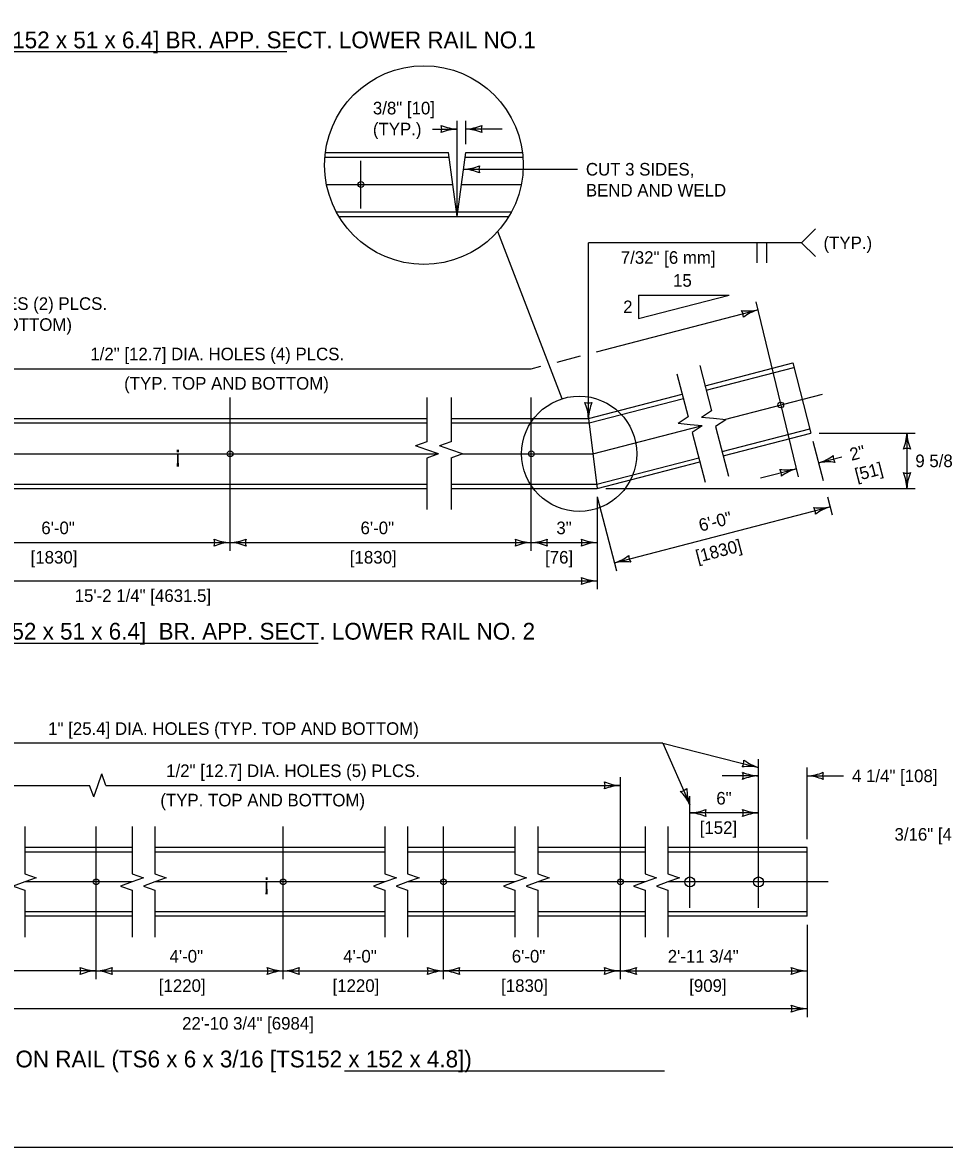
# Model space of a CAD drawing. Extents: x 49991.4 to 50021, y 49987.6 to 50011.4.
# Drawn here: x 50001.47 to 50005.86, y 49987.8 to 49993.16 of the extents above; entities that cross this region are included whole.
import ezdxf

# ---------------------------------------------------------------- set-up
doc = ezdxf.new("R2010")
doc.units = 0
for name, color, linetype in [('Level 1', 7, 'Continuous'), ('Level 2', 7, 'Continuous'), ('Level 3', 7, 'Continuous'), ('Level 4', 7, 'Continuous'), ('Level 5', 7, 'Continuous'), ('Level 6', 7, 'Continuous')]:
    doc.layers.add(name, color=color, linetype=linetype)

msp = doc.modelspace()

# ---------------------------------------------------------------- linework, layer by layer
at = {"layer": 'Level 1'}
for p, q in [((50002.9115, 49992.5433), (50003.499, 49992.5433)), ((50003.5403, 49992.2385), (50003.499, 49992.5433)), ((50003.5403, 49992.2385), (50003.5815, 49992.5433)), ((50003.5815, 49992.5433), (50003.8516, 49992.5433)), ((50002.9761, 49992.2385), (50003.787, 49992.2385)), ((50004.7222, 49991.4315), (50005.14, 49991.5399)), ((50005.14, 49991.5399), (50005.2267, 49991.2054)), ((50004.1662, 49991.2758), (50004.6135, 49991.3919)), ((50001.2445, 49991.2758), (50003.3956, 49991.2758)), ((50003.5108, 49991.2758), (50004.1662, 49991.2758)), ((50004.1662, 49991.2758), (50004.2084, 49990.9411)), ((50004.8089, 49991.0969), (50005.2267, 49991.2054)), ((50004.2084, 49990.9411), (50004.6974, 49991.068)), ((50001.2445, 49990.9411), (50003.3956, 49990.9411)), ((50003.5108, 49990.9411), (50004.2084, 49990.9411)), ((50001.9899, 49989.2289), (50001.4778, 49989.2289)), ((50003.1953, 49989.2289), (50002.0985, 49989.2289)), ((50003.8159, 49989.2289), (50003.3039, 49989.2289)), ((50004.4366, 49989.2289), (50003.9245, 49989.2289)), ((50005.2095, 49989.2289), (50004.5452, 49989.2289)), ((50005.2095, 49988.9014), (50005.2095, 49989.2289)), ((50001.9899, 49988.9014), (50001.4778, 49988.9014)), ((50003.1953, 49988.9014), (50002.0985, 49988.9014)), ((50003.8159, 49988.9014), (50003.3039, 49988.9014)), ((50004.4366, 49988.9014), (50003.9245, 49988.9014)), ((50005.2095, 49988.9014), (50004.5452, 49988.9014))]:
    msp.add_line(p, q, dxfattribs=at)
msp.add_lwpolyline([(49999.3835, 49998.9992), (50016.7501, 49998.9992), (50016.7501, 49987.7988), (49999.3835, 49987.7988)], close=True, dxfattribs=at)
for centre, radius in [((50003.0813, 49992.3909), 0.0137), ((50005.0833, 49991.3395), 0.0137), ((50002.4573, 49991.107), 0.0137), ((50003.8938, 49991.107), 0.0137), ((50001.8186, 49989.0651), 0.0136), ((50002.7107, 49989.0651), 0.0136), ((50003.4751, 49989.0651), 0.0136), ((50004.3186, 49989.0651), 0.0136), ((50004.65, 49989.0651), 0.0239), ((50004.9775, 49989.0651), 0.0239)]:
    msp.add_circle(centre, radius, dxfattribs=at)
at = {"layer": 'Level 2'}
for p, q in [((50001.1941, 49993.0245), (50002.7276, 49993.0245)), ((50001.111, 49990.2046), (50002.8772, 49990.2046)), ((50003.0022, 49988.1651), (50004.5293, 49988.1651))]:
    msp.add_line(p, q, dxfattribs=at)
at = {"layer": 'Level 3'}
for p, q in [((50003.5815, 49992.5833), (50003.5815, 49992.6954)), ((50003.422, 49992.6554), (50003.5403, 49992.6554)), ((50003.7549, 49992.6554), (50003.5815, 49992.6554)), ((50003.5707, 49992.4638), (50004.114, 49992.4638)), ((50004.0412, 49991.3694), (50003.7341, 49992.1672)), ((50005.1824, 49992.113), (50005.2489, 49992.1795)), ((50004.1662, 49991.2758), (50004.1665, 49992.113)), ((50005.1824, 49992.113), (50004.1665, 49992.113)), ((50004.9691, 49992.113), (50004.9691, 49992.0178)), ((50005.0148, 49992.113), (50005.0148, 49992.0178)), ((50005.1824, 49992.113), (50005.2489, 49992.0472)), ((50004.4056, 49991.8636), (50004.8375, 49991.8636)), ((50004.4056, 49991.8636), (50004.4056, 49991.7513)), ((50004.4056, 49991.7513), (50004.8375, 49991.8636)), ((50004.205, 49991.5936), (50004.9743, 49991.7932)), ((50004.0164, 49991.5446), (50004.1276, 49991.5735)), ((50001.034, 49991.5128), (50003.8938, 49991.5128)), ((50003.8938, 49991.5128), (50003.9389, 49991.5245)), ((50005.2667, 49991.2054), (50005.7249, 49991.2054)), ((50005.6849, 49991.2054), (50005.6849, 49990.9411)), ((50005.2368, 49991.1667), (50005.2853, 49990.9798)), ((50005.2637, 49991.0633), (50005.3746, 49991.0921)), ((50004.9871, 49990.9915), (50005.1564, 49991.0355)), ((50004.2084, 49990.9011), (50004.2084, 49990.4606)), ((50004.2084, 49990.9011), (50004.2084, 49990.8999)), ((50004.2084, 49990.9011), (50004.3, 49990.5483)), ((50004.2484, 49990.9411), (50005.7249, 49990.9411)), ((50005.3054, 49990.9024), (50005.3281, 49990.8151)), ((50004.2899, 49990.5871), (50005.318, 49990.8539)), ((50000.8491, 49990.6835), (50002.4573, 49990.6835)), ((50002.4573, 49990.6835), (50003.8938, 49990.6835)), ((50003.8938, 49990.6835), (50004.2084, 49990.6835)), ((50000.0841, 49990.5006), (50004.2084, 49990.5006)), ((50004.5215, 49989.7265), (50000.7474, 49989.7265)), ((50004.5215, 49989.7265), (50004.65, 49989.4343)), ((50004.5215, 49989.7265), (50004.9775, 49989.611)), ((50001.8262, 49989.5254), (50001.8456, 49989.5802)), ((50001.8651, 49989.5254), (50001.8456, 49989.5802)), ((50004.9775, 49989.571), (50004.8041, 49989.571)), ((50005.2095, 49989.2689), (50005.2095, 49989.611)), ((50005.2095, 49989.571), (50005.3829, 49989.571)), ((50000.975, 49989.5254), (50001.7874, 49989.5254)), ((50001.8068, 49989.4706), (50001.7874, 49989.5254)), ((50001.8068, 49989.4706), (50001.8262, 49989.5254)), ((50001.8651, 49989.5254), (50004.3186, 49989.5254)), ((50004.9775, 49989.3943), (50004.65, 49989.3943)), ((50005.2095, 49988.8614), (50005.2094, 49988.4208)), ((50001.8186, 49988.6408), (50000.975, 49988.6408)), ((50001.8186, 49988.6408), (50002.7107, 49988.6408)), ((50002.7107, 49988.6408), (50003.4751, 49988.6408)), ((50004.3186, 49988.6408), (50003.4751, 49988.6408)), ((50004.3186, 49988.6408), (50005.2095, 49988.6408)), ((50005.2094, 49988.4608), (50000.0842, 49988.4608))]:
    msp.add_line(p, q, dxfattribs=at)
for centre, radius in [((50003.3815, 49992.4837), 0.4738), ((50004.1222, 49991.107), 0.2747)]:
    msp.add_circle(centre, radius, dxfattribs=at)
for centre, radius, start, end in [((50003.4121, 49992.6554), 0.0548, 342.1388, 17.8612), ((50003.5518, 49992.8881), 0.233, 247.9228, 267.1727), ((50003.5723, 49992.8776), 0.2223, 272.3605, 292.544), ((50003.7097, 49992.6554), 0.0548, 162.1388, 197.8612), ((50003.5494, 49992.4333), 0.2223, 92.3605, 112.544), ((50003.57, 49992.4227), 0.233, 67.9228, 87.1727), ((50003.5616, 49992.6859), 0.2223, 272.3605, 292.544), ((50003.5592, 49992.231), 0.233, 67.9228, 87.1727), ((50003.6989, 49992.4638), 0.0548, 162.1388, 197.8612), ((50004.9274, 49992.0105), 0.2223, 262.0039, 282.1874), ((50004.8502, 49991.761), 0.0548, 356.6867, 32.4091), ((50005.0439, 49991.5709), 0.233, 107.3752, 126.6251), ((50003.944, 49991.2667), 0.2223, 2.3351, 22.5186), ((50004.1662, 49991.404), 0.0548, 252.1135, 287.8358), ((50004.3989, 49991.2642), 0.233, 157.8975, 177.1473), ((50005.4522, 49991.2169), 0.233, 337.9228, 357.1727), ((50005.907, 49991.2145), 0.2223, 182.3605, 202.544), ((50005.6849, 49991.0772), 0.0548, 72.1388, 107.8612), ((50005.1941, 49991.2857), 0.233, 287.3752, 306.6251), ((50005.3106, 49990.846), 0.2223, 82.0039, 102.1874), ((50005.3878, 49991.0955), 0.0548, 176.6867, 212.4091), ((50005.1094, 49991.2528), 0.2223, 262.0039, 282.1874), ((50005.0323, 49991.0033), 0.0548, 356.6867, 32.4091), ((50005.226, 49990.8131), 0.233, 107.3752, 126.6251), ((50005.6849, 49991.0693), 0.0548, 252.1388, 287.8612), ((50005.4522, 49990.9296), 0.233, 2.8273, 22.0772), ((50005.907, 49990.9319), 0.2223, 157.456, 177.6395), ((50005.2711, 49991.0712), 0.2223, 262.0039, 282.1874), ((50005.1939, 49990.8217), 0.0548, 356.6867, 32.4091), ((50005.3876, 49990.6315), 0.233, 107.3752, 126.6251), ((50002.4664, 49990.9056), 0.2223, 247.456, 267.6395), ((50002.329, 49990.6835), 0.0548, 342.1388, 17.8612), ((50002.4458, 49990.9162), 0.233, 272.8273, 292.0772), ((50002.5855, 49990.6835), 0.0548, 162.1388, 197.8612), ((50003.9029, 49990.9056), 0.2223, 247.456, 267.6395), ((50003.7656, 49990.6835), 0.0548, 342.1388, 17.8612), ((50003.8823, 49990.9162), 0.233, 272.8273, 292.0772), ((50004.022, 49990.6835), 0.0548, 162.1388, 197.8612), ((50004.0802, 49990.6835), 0.0548, 342.1388, 17.8612), ((50004.2199, 49990.9162), 0.233, 247.9228, 267.1727), ((50002.4687, 49990.4508), 0.233, 92.8273, 112.0772), ((50002.4481, 49990.4613), 0.2223, 67.456, 87.6395), ((50003.9053, 49990.4508), 0.233, 92.8273, 112.0772), ((50003.8846, 49990.4613), 0.2223, 67.456, 87.6395), ((50004.2176, 49990.4613), 0.2223, 92.3605, 112.544), ((50004.2253, 49990.7998), 0.2223, 286.9084, 307.0919), ((50004.3372, 49990.3589), 0.233, 82.4707, 101.7206), ((50004.414, 49990.6193), 0.0548, 176.6867, 212.4091), ((50004.0802, 49990.5006), 0.0548, 342.1388, 17.8612), ((50004.2199, 49990.7333), 0.233, 247.9228, 267.1727), ((50004.2176, 49990.2784), 0.2223, 92.3605, 112.544), ((50004.8532, 49989.6425), 0.0548, 327.9362, 3.6585), ((50004.9319, 49989.3935), 0.2223, 78.1578, 98.3413), ((50005.0458, 49989.8338), 0.233, 233.7202, 252.97), ((50004.8493, 49989.571), 0.0548, 342.1388, 17.8612), ((50004.989, 49989.8038), 0.233, 247.9228, 267.1727), ((50004.9867, 49989.3489), 0.2223, 92.3605, 112.544), ((50005.2004, 49989.7932), 0.2223, 272.3605, 292.544), ((50005.198, 49989.3383), 0.233, 67.9228, 87.1727), ((50005.3377, 49989.571), 0.0548, 162.1388, 197.8612), ((50004.3278, 49989.7475), 0.2223, 247.4558, 267.6393), ((50004.1904, 49989.5254), 0.0548, 342.1386, 17.861), ((50004.3301, 49989.2926), 0.233, 92.8271, 112.0769), ((50004.5984, 49989.5516), 0.0548, 275.8884, 311.6108), ((50004.8677, 49989.5175), 0.233, 181.6725, 200.9223), ((50004.4504, 49989.3364), 0.2223, 26.1101, 46.2936), ((50004.6409, 49989.6164), 0.2223, 272.3605, 292.544), ((50004.7783, 49989.3943), 0.0548, 162.1388, 197.8612), ((50004.9867, 49989.6164), 0.2223, 247.456, 267.6395), ((50004.8493, 49989.3943), 0.0548, 342.1388, 17.8612), ((50004.6386, 49989.1616), 0.233, 67.9228, 87.1727), ((50004.989, 49989.1616), 0.233, 92.8273, 112.0772), ((50001.6904, 49988.6408), 0.0548, 342.1388, 17.8612), ((50001.8301, 49988.8735), 0.233, 247.9228, 267.1727), ((50001.8071, 49988.8735), 0.233, 272.8273, 292.0772), ((50001.9468, 49988.6408), 0.0548, 162.1388, 197.8612), ((50002.7199, 49988.8629), 0.2223, 247.456, 267.6395), ((50002.5825, 49988.6408), 0.0548, 342.1388, 17.8612), ((50002.6992, 49988.8735), 0.233, 272.8273, 292.0772), ((50002.839, 49988.6408), 0.0548, 162.1388, 197.8612), ((50003.4842, 49988.8629), 0.2223, 247.456, 267.6395), ((50003.3468, 49988.6408), 0.0548, 342.1388, 17.8612), ((50003.4659, 49988.8629), 0.2223, 272.3605, 292.544), ((50003.6033, 49988.6408), 0.0548, 162.1388, 197.8612), ((50004.1904, 49988.6408), 0.0548, 342.1388, 17.8612), ((50004.3301, 49988.8735), 0.233, 247.9228, 267.1727), ((50004.3094, 49988.8629), 0.2223, 272.3605, 292.544), ((50004.4468, 49988.6408), 0.0548, 162.1388, 197.8612), ((50005.0813, 49988.6408), 0.0548, 342.1388, 17.8612), ((50005.221, 49988.8735), 0.233, 247.9228, 267.1727), ((50001.8277, 49988.4187), 0.2223, 92.3605, 112.544), ((50001.8094, 49988.4187), 0.2223, 67.456, 87.6395), ((50002.7222, 49988.4081), 0.233, 92.8273, 112.0772), ((50002.7016, 49988.4187), 0.2223, 67.456, 87.6395), ((50003.4866, 49988.4081), 0.233, 92.8273, 112.0772), ((50003.4636, 49988.4081), 0.233, 67.9228, 87.1727), ((50004.3278, 49988.4187), 0.2223, 92.3605, 112.544), ((50004.3071, 49988.4081), 0.233, 67.9228, 87.1727), ((50005.2186, 49988.4187), 0.2223, 92.3605, 112.544), ((50005.2186, 49988.6829), 0.2223, 247.456, 267.6395), ((50005.0812, 49988.4608), 0.0548, 342.1388, 17.8612), ((50005.2209, 49988.2281), 0.233, 92.8273, 112.0772)]:
    msp.add_arc(centre, radius, start, end, dxfattribs=at)
at = {"layer": 'Level 4'}
for p, q in [((50002.9093, 49992.5218), (50003.502, 49992.5218)), ((50003.5786, 49992.5218), (50003.8538, 49992.5218)), ((50002.9639, 49992.26), (50003.7992, 49992.26)), ((50004.7275, 49991.4107), (50005.1454, 49991.5191)), ((50004.1689, 49991.2543), (50004.6189, 49991.3711)), ((50001.2445, 49991.2542), (50003.3956, 49991.2542)), ((50003.5108, 49991.2542), (50004.1689, 49991.2543)), ((50004.8037, 49991.1171), (50005.2215, 49991.2255)), ((50004.2057, 49990.9626), (50004.6922, 49991.0883)), ((50001.2445, 49990.9626), (50003.3956, 49990.9626)), ((50003.5108, 49990.9626), (50004.2057, 49990.9626)), ((50001.9899, 49989.2074), (50001.4778, 49989.2074)), ((50003.1953, 49989.2074), (50002.0985, 49989.2074)), ((50003.8159, 49989.2074), (50003.3039, 49989.2074)), ((50004.4366, 49989.2074), (50003.9245, 49989.2074)), ((50005.2095, 49989.2073), (50004.5452, 49989.2073)), ((50001.9899, 49988.9229), (50001.4778, 49988.9229)), ((50003.1953, 49988.9229), (50002.0985, 49988.9229)), ((50003.8159, 49988.9229), (50003.3039, 49988.9229)), ((50004.4366, 49988.9229), (50003.9245, 49988.9229)), ((50005.2095, 49988.9229), (50004.5452, 49988.9229))]:
    msp.add_line(p, q, dxfattribs=at)
at = {"layer": 'Level 5'}
for p, q in [((50003.5403, 49992.2385), (50003.5403, 49992.6954)), ((50003.0813, 49992.2773), (50003.0813, 49992.5046)), ((50002.9169, 49992.3909), (50003.5197, 49992.3909)), ((50003.5609, 49992.3909), (50003.8462, 49992.3909)), ((50004.965, 49991.8321), (50005.1657, 49990.9966)), ((50004.8155, 49991.27), (50005.2818, 49991.391)), ((50002.4573, 49990.6435), (50002.4573, 49991.3758)), ((50003.8938, 49990.6435), (50003.8938, 49991.3758)), ((50004.1875, 49991.107), (50004.7041, 49991.241)), ((50001.1923, 49991.107), (50003.448, 49991.107)), ((50003.5631, 49991.107), (50004.1875, 49991.107)), ((50004.9775, 49988.9413), (50004.9775, 49989.6511)), ((50004.3186, 49988.6008), (50004.3186, 49989.5654)), ((50004.65, 49988.9413), (50004.65, 49989.4743)), ((50001.8186, 49988.6008), (50001.8186, 49989.3289)), ((50002.7107, 49988.6008), (50002.7107, 49989.3289)), ((50003.4751, 49988.6008), (50003.4751, 49989.3289)), ((50001.9899, 49989.0651), (50001.4778, 49989.0651)), ((50003.1953, 49989.0651), (50002.0985, 49989.0651)), ((50003.8159, 49989.0651), (50003.3039, 49989.0651)), ((50004.4366, 49989.0651), (50003.9245, 49989.0651)), ((50005.3095, 49989.0651), (50004.5452, 49989.0651))]:
    msp.add_line(p, q, dxfattribs=at)
at = {"layer": 'Level 6'}
for p, q in [((50004.6971, 49991.5283), (50004.7531, 49991.3121)), ((50004.5884, 49991.4887), (50004.6417, 49991.2832)), ((50003.3956, 49991.3758), (50003.3956, 49991.1643)), ((50003.5108, 49991.3758), (50003.5108, 49991.1643)), ((50004.6416, 49991.2832), (50004.5934, 49991.2506)), ((50004.753, 49991.312), (50004.7048, 49991.2795)), ((50004.7627, 49991.2745), (50004.7048, 49991.2795)), ((50004.6513, 49991.2456), (50004.5934, 49991.2506)), ((50004.7092, 49991.2406), (50004.6513, 49991.2456)), ((50004.7092, 49991.2406), (50004.6611, 49991.2079)), ((50004.8207, 49991.2695), (50004.7627, 49991.2745)), ((50004.8207, 49991.2695), (50004.7725, 49991.2368)), ((50004.7726, 49991.2369), (50004.834, 49991.0001)), ((50004.6612, 49991.208), (50004.7225, 49990.9712)), ((50003.3956, 49991.1643), (50003.3408, 49991.1449)), ((50003.3956, 49991.1255), (50003.3408, 49991.1449)), ((50003.4504, 49991.1061), (50003.3956, 49991.1255)), ((50003.5107, 49991.1643), (50003.4559, 49991.1449)), ((50003.5107, 49991.1255), (50003.4559, 49991.1449)), ((50003.5655, 49991.1061), (50003.5107, 49991.1255)), ((50003.4504, 49991.1061), (50003.3956, 49991.0866)), ((50003.3956, 49991.0866), (50003.3956, 49990.8411)), ((50003.5655, 49991.1061), (50003.5107, 49991.0866)), ((50003.5108, 49991.0866), (50003.5108, 49990.8411)), ((50001.4778, 49989.3289), (50001.4778, 49989.1039)), ((50001.9899, 49989.3289), (50001.9899, 49989.104)), ((50002.0985, 49989.3289), (50002.0985, 49989.1039)), ((50003.1953, 49989.3289), (50003.1953, 49989.104)), ((50003.3039, 49989.3289), (50003.3039, 49989.1039)), ((50003.8159, 49989.3289), (50003.8159, 49989.104)), ((50003.9245, 49989.3289), (50003.9245, 49989.1039)), ((50004.4366, 49989.3289), (50004.4366, 49989.104)), ((50004.5452, 49989.3289), (50004.5452, 49989.1039)), ((50001.4778, 49989.1039), (50001.5326, 49989.0845)), ((50001.5326, 49989.0845), (50001.4778, 49989.0651)), ((50001.9899, 49989.104), (50002.0447, 49989.0846)), ((50002.0447, 49989.0846), (50001.9899, 49989.0652)), ((50002.0985, 49989.1039), (50002.1533, 49989.0845)), ((50002.1533, 49989.0845), (50002.0985, 49989.0651)), ((50003.1953, 49989.104), (50003.2501, 49989.0846)), ((50003.2501, 49989.0846), (50003.1953, 49989.0652)), ((50003.3039, 49989.1039), (50003.3587, 49989.0845)), ((50003.3587, 49989.0845), (50003.3039, 49989.0651)), ((50003.8159, 49989.104), (50003.8707, 49989.0846)), ((50003.8707, 49989.0846), (50003.8159, 49989.0652)), ((50003.9245, 49989.1039), (50003.9793, 49989.0845)), ((50003.9793, 49989.0845), (50003.9245, 49989.0651)), ((50004.4366, 49989.104), (50004.4914, 49989.0846)), ((50004.4914, 49989.0846), (50004.4366, 49989.0652)), ((50004.5452, 49989.1039), (50004.6, 49989.0845)), ((50004.6, 49989.0845), (50004.5452, 49989.0651)), ((50001.4778, 49989.0651), (50001.423, 49989.0457)), ((50001.423, 49989.0457), (50001.4778, 49989.0261)), ((50001.4778, 49989.0261), (50001.4778, 49988.8014)), ((50001.9899, 49989.0652), (50001.9351, 49989.0458)), ((50001.9351, 49989.0458), (50001.9899, 49989.0262)), ((50001.9899, 49989.0262), (50001.9899, 49988.8014)), ((50002.0985, 49989.0651), (50002.0437, 49989.0457)), ((50002.0437, 49989.0457), (50002.0985, 49989.0261)), ((50002.0985, 49989.0261), (50002.0985, 49988.8014)), ((50003.1953, 49989.0652), (50003.1405, 49989.0458)), ((50003.1405, 49989.0458), (50003.1953, 49989.0262)), ((50003.1953, 49989.0262), (50003.1953, 49988.8014)), ((50003.3039, 49989.0651), (50003.2491, 49989.0457)), ((50003.2491, 49989.0457), (50003.3039, 49989.0261)), ((50003.3039, 49989.0261), (50003.3039, 49988.8014)), ((50003.8159, 49989.0652), (50003.7611, 49989.0458)), ((50003.7611, 49989.0458), (50003.8159, 49989.0262)), ((50003.8159, 49989.0262), (50003.8159, 49988.8014)), ((50003.9245, 49989.0651), (50003.8697, 49989.0457)), ((50003.8697, 49989.0457), (50003.9245, 49989.0261)), ((50003.9245, 49989.0261), (50003.9245, 49988.8014)), ((50004.4366, 49989.0652), (50004.3818, 49989.0458)), ((50004.3818, 49989.0458), (50004.4366, 49989.0262)), ((50004.4366, 49989.0262), (50004.4366, 49988.8014)), ((50004.5452, 49989.0651), (50004.4904, 49989.0457)), ((50004.4904, 49989.0457), (50004.5452, 49989.0261)), ((50004.5452, 49989.0261), (50004.5452, 49988.8014))]:
    msp.add_line(p, q, dxfattribs=at)

# ---------------------------------------------------------------- texts
at = {"layer": 'Level 2'}
for s, height, p in [('TS6 x 2 x 1/4 [TS152 x 51 x 6.4] BR. APP. SECT. LOWER RAIL NO.1', 0.08, (50000.5919, 49993.0405)), ('3/8" [10]', 0.06, (50003.1383, 49992.7254)), ('(TYP.)', 0.06, (50003.1383, 49992.6254)), ('CUT 3 SIDES,', 0.06, (50004.154, 49992.4338)), ('BEND AND WELD', 0.06, (50004.154, 49992.3338)), ('(TYP.)', 0.06, (50005.2871, 49992.083)), (' 7/32" [6 mm]', 0.06, (50004.2981, 49992.013)), ('15', 0.06, (50004.5697, 49991.9036)), ('1" [25.4] DIA. HOLES (2) PLCS.', 0.06, (50000.7273, 49991.7931)), ('2', 0.06, (50004.3316, 49991.7775)), ('(TYP. TOP AND BOTTOM)', 0.06, (50000.7273, 49991.6931)), (' 1/2" [12.7] DIA. HOLES (4) PLCS. ', 0.06, (50001.7685, 49991.5528)), ('(TYP. TOP AND BOTTOM)', 0.06, (50001.9521, 49991.4128)), ('¡', 0.08, (50002.1904, 49991.0645)), ('9 5/8" [244]', 0.06, (50005.7249, 49991.0432)), ('6\'-0"', 0.06, (50001.5571, 49990.7235)), ('6\'-0"', 0.06, (50003.0794, 49990.7235)), ('3"', 0.06, (50004.0131, 49990.7235)), ('[1830]', 0.06, (50001.5061, 49990.5835)), ('[1830]', 0.06, (50003.0285, 49990.5835)), ('[76]', 0.06, (50003.9592, 49990.5835)), ('15\'-2 1/4" [4631.5]', 0.06, (50001.7163, 49990.4006)), ('TS6 x 2 x 1/4 [TS152 x 51 x 6.4]  BR. APP. SECT. LOWER RAIL NO. 2', 0.08, (50000.5287, 49990.2206)), ('1" [25.4] DIA. HOLES (TYP. TOP AND BOTTOM)', 0.06, (50001.59, 49989.7665)), (' 1/2" [12.7] DIA. HOLES (5) PLCS.', 0.06, (50002.1304, 49989.5654)), ('4 1/4" [108]', 0.06, (50005.4229, 49989.541)), ('(TYP. TOP AND BOTTOM)', 0.06, (50002.1247, 49989.4254)), ('6"', 0.06, (50004.7758, 49989.4343)), ('[152]', 0.06, (50004.6967, 49989.2943)), (' 3/16" [4.8] THICK', 0.06, (50005.6034, 49989.2621)), ('¡', 0.08, (50002.6134, 49989.0251)), ('4\'-0"', 0.06, (50002.1686, 49988.6808)), ('4\'-0"', 0.06, (50002.9968, 49988.6808)), ('6\'-0"', 0.06, (50003.8007, 49988.6808)), ('2\'-11 3/4"', 0.06, (50004.5443, 49988.6808)), ('[1220]', 0.06, (50002.1176, 49988.5408)), ('[1220]', 0.06, (50002.9459, 49988.5408)), ('[1830]', 0.06, (50003.7498, 49988.5408)), ('[909]', 0.06, (50004.6467, 49988.5408)), ('22\'-10 3/4" [6984]', 0.06, (50002.2287, 49988.3608)), ('TRANSITION RAIL (TS6 x 6 x 3/16 [TS152 x 152 x 4.8])', 0.08, (50000.9464, 49988.1808))]:
    msp.add_text(s, height=height, dxfattribs=at).set_placement(p)
for s, p in [('2"', (50005.4208, 49991.0731)), ('[51]', (50005.4459, 49990.9763)), ('6\'-0"', (50004.7009, 49990.735)), ('[1830]', (50004.6868, 49990.5867))]:
    msp.add_text(s, height=0.06, rotation=14.5479, dxfattribs=at).set_placement(p)

doc.saveas('drawing.dxf')
